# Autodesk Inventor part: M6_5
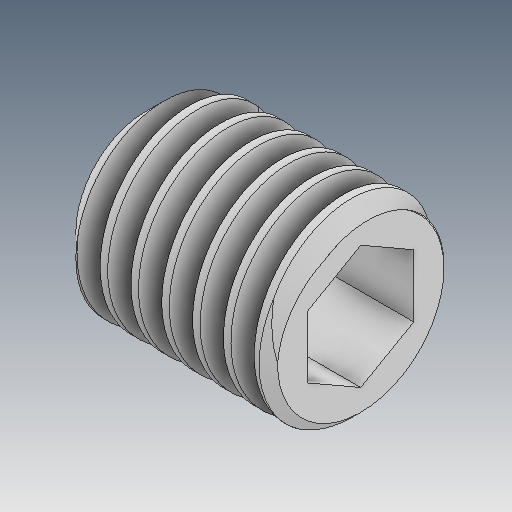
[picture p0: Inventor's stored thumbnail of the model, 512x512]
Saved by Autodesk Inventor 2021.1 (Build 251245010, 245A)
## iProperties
Created: 2019-04
Part Number: M6_5
Material: Ogólny
Document SubType Name: Modeling
Designer: user
Density: 1 g/cm^3
Appearance: Domyślna
Author: user
Revision Number: ÈÎºÎ
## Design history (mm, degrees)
feature "ÊäÈë1"
node "Bryła1"
